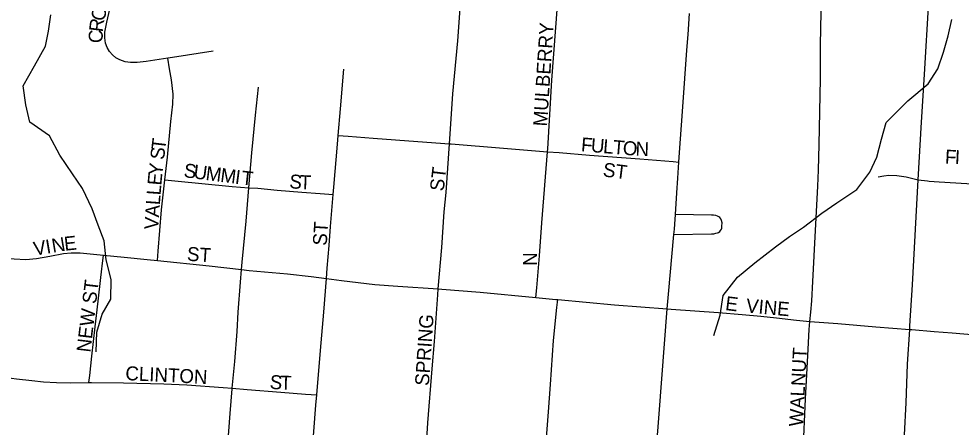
# Model space of a CAD drawing. Extents: x 1442749 to 1756758, y 235267 to 677782.
# Drawn here: x 1591124 to 1594493, y 530721 to 532182 of the extents above; entities that cross this region are included whole.
import ezdxf

# ---------------------------------------------------------------- set-up
doc = ezdxf.new("R2010")
doc.units = 0
for name, color, linetype in [('GM_X_City_Street', 7, 'Continuous'), ('GM_X_City_Street_Text', 7, 'Continuous'), ('GM_X_Minor_River', 7, 'Continuous'), ('GM_X_State_Route', 7, 'Continuous'), ('GM_X_US_Route', 7, 'Continuous')]:
    doc.layers.add(name, color=color, linetype=linetype)

msp = doc.modelspace()

# ---------------------------------------------------------------- linework, layer by layer
at = {"layer": 'GM_X_City_Street'}
for points in [[(1592663.4, 531734.9), (1592676, 531913.5), (1592692.9, 532102.9), (1592707.4, 532302.3), (1592726.2, 532540.9), (1592733.9, 532635.6), (1592738.6, 532680.3), (1592746.1, 532732.3), (1592751.6, 532759)], [(1593014.2, 531706.2), (1593015, 531716.5), (1593029.4, 531962), (1593056.4, 532325.1), (1593064.3, 532472.7), (1593067.4, 532504.7)], [(1591656.9, 532041), (1591579.1, 532029.4), (1591546.6, 532025.1), (1591523.6, 532025.3), (1591504.2, 532028.3), (1591485.7, 532034.7), (1591471.3, 532042.6), (1591458.6, 532052.9), (1591448, 532065.5), (1591439.8, 532079.6), (1591434.2, 532095), (1591431, 532114.4), (1591431.5, 532134), (1591438.4, 532169.4), (1591459, 532259), (1591466.1, 532277.3), (1591476, 532294.2), (1591488.4, 532309.6), (1591500.9, 532320.1), (1591518.1, 532329.5), (1591536.8, 532335.5), (1591662.8, 532357.6), (1591772.8, 532375.9)], [(1593951.7, 531099.4), (1593955.4, 531132.1), (1593958.8, 531173.2), (1593962.6, 531242.6), (1593971.5, 531424.3), (1593980.2, 531583), (1593982.3, 531640.4), (1593984.7, 531731.8), (1593989.3, 531967.3), (1593990.1, 532088.2), (1593991.7, 532206.1), (1593992.2, 532220.1), (1593992.8, 532231.9), (1593994.2, 532246.2)], [(1591646, 531605.4), (1591655.1, 531687.4), (1591667.7, 531814.8), (1591674.3, 531876.7), (1591675.2, 531912.3), (1591669.3, 531963.8), (1591663.1, 532002.6), (1591656.9, 532041)], [(1591819.1, 532065.8), (1591673.2, 532043.4), (1591656.9, 532041)], [(1592265.9, 531764.2), (1592273.7, 531859.3), (1592285.6, 532001.3)], [(1591946.8, 531577.5), (1591957.4, 531702.5), (1591970.2, 531836.6), (1591980.6, 531937.7)], [(1592248.1, 531552.9), (1592250.4, 531579.9), (1592263.4, 531733.8), (1592265.9, 531764.2)], [(1592265.9, 531764.2), (1592301.5, 531761.6), (1592391.2, 531755.3), (1592549.9, 531743.4), (1592663.4, 531734.9)], [(1592623.1, 531215.5), (1592635.8, 531364.2), (1592644.2, 531491.8), (1592651.1, 531560.3), (1592663.4, 531734.9)], [(1592663.4, 531734.9), (1592669.9, 531734.4), (1592856.3, 531719.1), (1593014.2, 531706.2)], [(1592972.6, 531184.8), (1592975.6, 531219.4), (1592985.3, 531333.8), (1592993.7, 531451.6), (1593014.2, 531706.2)], [(1593014.2, 531706.2), (1593055.7, 531703.3), (1593163.6, 531694.3), (1593344.5, 531680.7), (1593463.5, 531671.1), (1593483.8, 531669.5)], [(1591619.3, 531316.8), (1591622.1, 531350.6), (1591634.1, 531498), (1591646, 531605.4)], [(1591646, 531605.4), (1591681.4, 531602), (1591887.2, 531582.5), (1591946.8, 531577.5)], [(1594195.8, 531616.9), (1594215.9, 531620.5), (1594234, 531622), (1594263.1, 531620.8), (1594296, 531616.5), (1594339.4, 531606)], [(1594339.4, 531606), (1594372, 531602), (1594378.5, 531601.2), (1594414.4, 531598.4), (1594512.4, 531592.2), (1594584.4, 531589.8), (1594627, 531589.6), (1594685.9, 531591.4), (1594716.4, 531593.6), (1594741.4, 531597.5), (1594765.4, 531602.6)], [(1591920.2, 531285.1), (1591922.2, 531311.7), (1591936.2, 531457.9), (1591946.8, 531577.5)], [(1591946.8, 531577.5), (1591978.7, 531575.8), (1592047.2, 531569), (1592135.5, 531561.9), (1592200.9, 531556.7), (1592248.1, 531552.9)], [(1592223.8, 531252.8), (1592226.8, 531289.3), (1592233, 531371), (1592238.4, 531439.5), (1592248.1, 531552.9)], [(1593466, 531410.6), (1593600.2, 531412.5), (1593608.2, 531413.1), (1593615.3, 531414.5), (1593621, 531416.1), (1593625.6, 531417.9), (1593629.9, 531421.1), (1593632.8, 531424.8), (1593635.4, 531429.3), (1593636.6, 531433.5), (1593637.6, 531439.7), (1593637.9, 531452.2), (1593636.1, 531460.8), (1593633.5, 531466.3), (1593629.7, 531470.9), (1593626.2, 531473.3), (1593621.9, 531475.9), (1593615.7, 531477.9), (1593607.7, 531479.1), (1593600.3, 531479.7), (1593471.1, 531482.3)], [(1591078.3, 531325.6), (1591106.9, 531322.9), (1591149, 531320.7), (1591187.5, 531323.9), (1591235.4, 531332.8), (1591284, 531342.9), (1591310.6, 531345.3), (1591343.8, 531344.8), (1591426.6, 531336.6)], [(1591374.8, 530880.7), (1591377.6, 530906), (1591385.3, 530975.6), (1591397.3, 531079.6), (1591404.6, 531141.3), (1591421, 531287.7), (1591422.1, 531297.4), (1591426.6, 531336.6)], [(1591426.6, 531336.6), (1591500.8, 531329.4), (1591582.3, 531320.7), (1591619.3, 531316.8)], [(1591619.3, 531316.8), (1591804.2, 531297.8), (1591920.2, 531285.1)], [(1591887.2, 530860.6), (1591895.9, 530955.7), (1591904, 531063.6), (1591908.6, 531132.2), (1591917, 531239.8), (1591920.2, 531285.1)], [(1591920.2, 531285.1), (1591947.6, 531282.1), (1592084.8, 531269.2), (1592169.6, 531260), (1592223.8, 531252.8)], [(1592189.4, 530836.4), (1592202.9, 530995.3), (1592213.8, 531132.5), (1592223.8, 531252.8)], [(1592223.8, 531252.8), (1592277.7, 531245.7), (1592397.1, 531231.9), (1592478.7, 531225.1), (1592623.1, 531215.5)], [(1592573.6, 530522.8), (1592585.8, 530736.9), (1592601.4, 530929.6), (1592609.7, 531027.5), (1592621.3, 531194.3), (1592623.1, 531215.5)], [(1592623.1, 531215.5), (1592635.8, 531214.7), (1592773.2, 531203.6), (1592972.6, 531184.8)], [(1592972.6, 531184.8), (1593044.2, 531178.1), (1593050.4, 531177.6)], [(1592994.4, 530485.4), (1593000.3, 530560.4), (1593017.9, 530776.1), (1593025, 530874.3), (1593035.7, 531031.4), (1593047.5, 531148.8), (1593050.4, 531177.6)], [(1593050.4, 531177.6), (1593253.1, 531159.2), (1593441.9, 531143.9)], [(1593441.9, 531143.9), (1593455.4, 531143), (1593625, 531130.9), (1593709.8, 531124.4), (1593776.8, 531117.9), (1593832.8, 531112.7), (1593904.5, 531104.4), (1593951.7, 531099.4)], [(1593927.3, 530631.3), (1593936.1, 530822), (1593940.5, 530909.9), (1593945.1, 531000.7), (1593949.4, 531070.5), (1593951.7, 531099.4)], [(1593951.7, 531099.4), (1594051.6, 531091.4), (1594188, 531080.4), (1594308.6, 531070.7)], [(1594308.6, 531070.7), (1594316.3, 531070.1), (1594396.1, 531063.7), (1594460.3, 531058.4), (1594613.7, 531045.6), (1594655.7, 531042.1), (1594697.4, 531039.1), (1594730.1, 531037.2)], [(1591025.2, 530906.5), (1591061.8, 530901.2), (1591115.3, 530894), (1591170.8, 530887.5), (1591212.8, 530883.8), (1591259.2, 530880.9), (1591308.5, 530880.1), (1591374.8, 530880.7)], [(1591374.8, 530880.7), (1591384, 530880.8), (1591498.6, 530879.2), (1591642.7, 530876.2), (1591724.4, 530872.6), (1591855.1, 530863.1), (1591887.2, 530860.6)], [(1591856.2, 530355.2), (1591851.9, 530363.2), (1591849.4, 530370.2), (1591847.8, 530381.7), (1591848.3, 530394.7), (1591855.2, 530466.1), (1591861.4, 530537.9), (1591871, 530658.6), (1591879.4, 530769.7), (1591887, 530857.7), (1591887.2, 530860.6)], [(1591887.2, 530860.6), (1591940, 530856.3), (1592060.9, 530846.5), (1592149.3, 530839.6), (1592189.4, 530836.4)], [(1592167, 530559.8), (1592169.7, 530595.7), (1592186.3, 530799.3), (1592189.4, 530836.4)]]:
    msp.add_lwpolyline(points, dxfattribs=at)
at = {"layer": 'GM_X_Minor_River'}
for points in [[(1591400.7, 530990.7), (1591403.5, 531060.8), (1591422.3, 531124.8), (1591453, 531178.6), (1591453.8, 531248.8), (1591436.6, 531319.2), (1591429.4, 531387.5), (1591408, 531443.9), (1591386.7, 531502.3), (1591351.5, 531574.9), (1591316, 531627.5), (1591270.7, 531694.2), (1591233.4, 531762.8), (1591163.9, 531811.8), (1591148.6, 531874.1), (1591139.3, 531942.4), (1591180.3, 532014.2), (1591219.2, 532083.9), (1591229.9, 532138), (1591238.5, 532196)], [(1593608.1, 531049.6), (1593631, 531121.5), (1593641.9, 531191.6), (1593692.7, 531257.2), (1593755.5, 531308.6), (1593828.3, 531366), (1593878.9, 531403.5), (1593929.4, 531437), (1593994.1, 531486.4), (1594048.7, 531523.9), (1594119.4, 531571.2), (1594166.2, 531632.9), (1594190.9, 531686.8), (1594207.7, 531750.8), (1594224.4, 531810.7), (1594301.5, 531888.1), (1594374.4, 531949.4), (1594409.1, 532003.2), (1594429.8, 532063.1), (1594446.6, 532121.1), (1594459.3, 532179.1)]]:
    msp.add_lwpolyline(points, dxfattribs=at)
at = {"layer": 'GM_X_State_Route'}
msp.add_lwpolyline([(1594237.7, 529944.2), (1594240.6, 529970.4), (1594243.3, 529994.1), (1594257.3, 530200.4), (1594276.7, 530504.6), (1594283.5, 530602.2), (1594289.9, 530693.6), (1594295.9, 530808.2), (1594301, 530946.6), (1594308.6, 531070.7), (1594309.3, 531083.1), (1594318.7, 531229.9), (1594339.4, 531606), (1594350.8, 531812.7), (1594362.1, 531982.7), (1594376.9, 532244.7), (1594380, 532301.1)], dxfattribs=at)
at = {"layer": 'GM_X_US_Route'}
for points in [[(1593512.5, 532069.4), (1593516.6, 532125.8), (1593521.3, 532200.9)], [(1593403.4, 530645.9), (1593413.1, 530768.8), (1593441.9, 531143.9), (1593446, 531197.4), (1593466, 531410.6), (1593467.4, 531429.8), (1593468.6, 531447.5), (1593471.1, 531482.3), (1593476.5, 531559.2), (1593480.2, 531612.1), (1593483.8, 531669.5), (1593484.9, 531687), (1593497.8, 531867.2), (1593512.5, 532069.4)]]:
    msp.add_lwpolyline(points, dxfattribs=at)

# ---------------------------------------------------------------- texts
at = {"layer": 'GM_X_City_Street_Text'}
for s, rotation, p in [('O', 76.8759, (1591428.9, 532170.7)), ('R', 82.9412, (1591424.2, 532132.7)), ('C', 89.1503, (1591423.7, 532094.6)), ('MULBERRY', 86.2818, (1593012.1, 531795.9)), ('T', 83.2796, (1591647.2, 531710.8)), ('F', 355.3498, (1593132.4, 531708.1)), ('U', 355.318, (1593167.4, 531705.3)), ('L', 355.3418, (1593211.3, 531701.7)), ('T', 355.3498, (1593246.4, 531698.8)), ('O', 355.318, (1593281.5, 531696)), ('N', 357.8535, (1593327.7, 531692.3)), ('S', 83.2614, (1591643, 531675.9)), ('F', 357.3218, (1594433.9, 531664.1)), ('I', 357.2882, (1594469, 531662.5)), ('Y', 83.4932, (1591636.5, 531619.1)), ('ST', 352.8514, (1593210, 531618.3)), ('S', 352.6581, (1591711.6, 531615.7)), ('U', 352.6781, (1591746.5, 531611.2)), ('M', 352.6858, (1591790.1, 531605.6)), ('M', 352.6942, (1591842.5, 531598.9)), ('I', 352.6364, (1591894.9, 531592.2)), ('T', 353.8832, (1591917.9, 531589.2)), ('ST', 83.2961, (1592642.6, 531563.4)), ('E', 84.7734, (1591633.4, 531584.4)), ('S', 355.2954, (1592089.7, 531576.2)), ('T', 357.8338, (1592127.2, 531573.1)), ('L', 85.8171, (1591630.8, 531549.5)), ('L', 85.8233, (1591628.2, 531514.4)), ('A', 85.804, (1591625, 531470.5)), ('V', 85.7991, (1591621.8, 531426.6)), ('ST', 86.4254, (1592224.6, 531369.3)), ('N', 9.4839, (1591245.8, 531344.9)), ('E', 6.132, (1591288.5, 531352)), ('V', 9.4408, (1591180.7, 531334)), ('I', 9.4971, (1591224.1, 531341.2)), ('ST', 356.4254, (1591724.1, 531316.5)), ('N', 90, (1592976.9, 531298.3)), ('NEW ST', 83.2979, (1591379.8, 530987)), ('E', 352.8817, (1593647.5, 531140.4)), ('VINE', 354.8086, (1593722, 531131.7)), ('SPRING', 86.1183, (1592589.8, 530867.9)), ('WALNUT', 87.139, (1593927.3, 530722.4)), ('CLINTON', 357.186, (1591504, 530889.7)), ('S', 355.0208, (1592019.5, 530858.9)), ('T', 358.2096, (1592057.6, 530855.7))]:
    msp.add_text(s, height=50, rotation=rotation, dxfattribs=at).set_placement(p)

doc.saveas('drawing.dxf')
